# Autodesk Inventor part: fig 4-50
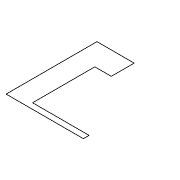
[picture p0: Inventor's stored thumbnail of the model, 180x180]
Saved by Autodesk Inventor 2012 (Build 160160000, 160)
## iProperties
Created: 2004-05
Part Number: fig 4-50
Document SubType Name: Modeling
Designer: CADCIM Technologies
Manufacturer: Standard
Standards Organization: Custom
Density: 1 g/cm^3
Material: Default
Author: CADCIM Technologies
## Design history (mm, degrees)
sketch "Sketch1"
  geometry: L1 (30.083, 49.92)-(16.646, 49.92); L2 (16.646, 49.92)-(16.646, 17.104); L3 (16.646, 17.104)-(44.553, 17.104); L4 (44.553, 17.104)-(44.553, 19.171); L5 (44.553, 19.171)-(24.139, 19.171); L6 (24.139, 19.171)-(24.139, 41.652); L7 (24.139, 41.652)-(30.083, 41.652); L8 (30.083, 41.652)-(30.083, 49.92)
  constraints: 16 end point, 1 horizontal, 1 other
